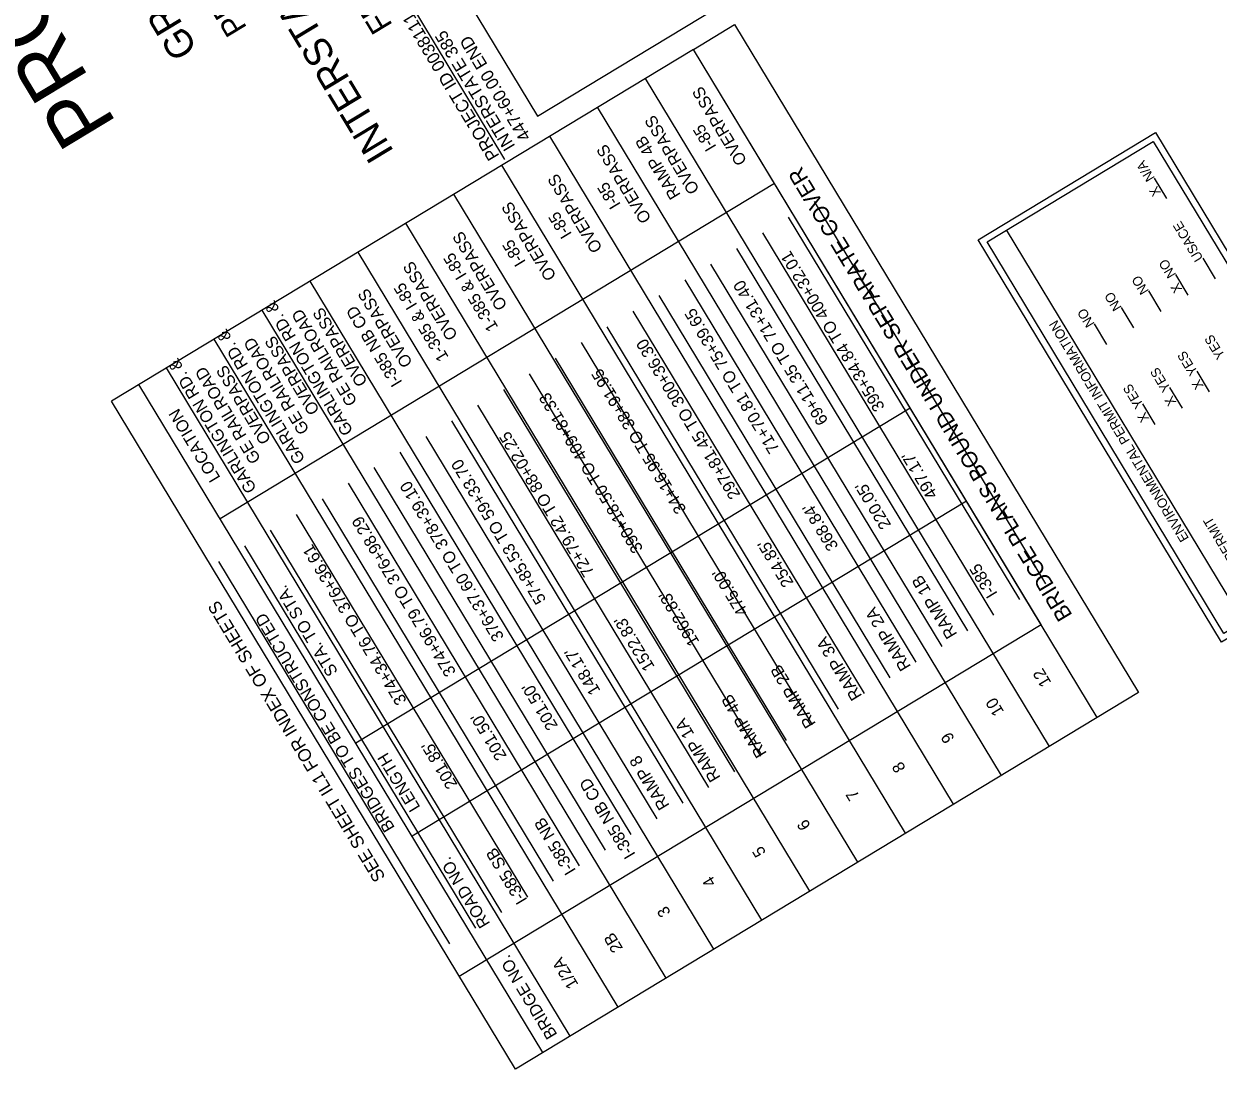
# Model space of a CAD drawing. Extents: x 2640307 to 2643631, y 679117 to 682232.
# Drawn here: x 2642228 to 2642974, y 679932 to 680585 of the extents above; entities that cross this region are included whole.
import ezdxf

# ---------------------------------------------------------------- set-up
doc = ezdxf.new("R2010")
doc.units = 0
for name, color, linetype in [('Level 3', 7, 'Continuous'), ('Level 42', 7, 'Continuous'), ('Level 63', 7, 'Continuous'), ('RD_SHT_Bndy', 7, 'Continuous'), ('RD_SHT_TX', 7, 'Continuous'), ('RD_TX_TitleSht', 7, 'Continuous')]:
    doc.layers.add(name, color=color, linetype=linetype)

msp = doc.modelspace()

# ---------------------------------------------------------------- linework, layer by layer
at = {"layer": 'Level 3'}
for p, q in [((2642646.09, 680569.52), (2642282.38, 680349.66)), ((2642863.36, 680210.08), (2642646.09, 680569.52)), ((2642898.53, 680151.89), (2642646.09, 680569.52)), ((2642868.58, 680133.78), (2642616.14, 680551.41)), ((2642838.63, 680115.67), (2642586.19, 680533.31)), ((2642808.68, 680097.57), (2642556.23, 680515.2)), ((2642778.72, 680079.46), (2642526.28, 680497.1)), ((2642696.79, 680485.65), (2642350.19, 680276.14)), ((2642748.77, 680061.36), (2642496.33, 680478.99)), ((2642718.82, 680043.25), (2642466.37, 680460.88)), ((2642688.86, 680025.15), (2642436.42, 680442.78)), ((2642658.91, 680007.04), (2642406.47, 680424.67)), ((2642628.96, 679988.94), (2642376.51, 680406.57)), ((2642599, 679970.83), (2642346.56, 680388.46)), ((2642569.05, 679952.72), (2642316.61, 680370.36)), ((2642551.93, 679942.38), (2642299.49, 680360.01)), ((2642534.82, 679932.03), (2642282.38, 680349.66)), ((2642781.63, 680345.3), (2642435.02, 680135.79)), ((2642816.8, 680287.1), (2642470.2, 680077.6)), ((2642898.53, 680151.89), (2642534.82, 679932.03))]:
    msp.add_line(p, q, dxfattribs=at)
at = {"layer": 'Level 42'}
msp.add_lwpolyline([(2642898.53, 680151.89), (2642646.09, 680569.52), (2642671.77, 680585.04), (2642924.21, 680167.4)], close=True, dxfattribs=at)
at = {"layer": 'Level 63'}
for p, q in [((2642866.28, 680235.36), (2642721.8, 680474.4)), ((2642850.1, 680225.57), (2642705.61, 680464.61)), ((2642833.9, 680215.78), (2642689.41, 680454.81)), ((2642817.7, 680205.99), (2642673.21, 680445.03)), ((2642801.51, 680196.2), (2642657.02, 680435.24)), ((2642785.32, 680186.41), (2642640.83, 680425.45)), ((2642769.11, 680176.62), (2642624.63, 680415.65)), ((2642752.93, 680166.84), (2642608.44, 680405.86)), ((2642736.73, 680157.04), (2642592.24, 680396.08)), ((2642720.53, 680147.26), (2642576.06, 680386.29)), ((2642704.34, 680137.47), (2642559.86, 680376.5)), ((2642688.14, 680127.68), (2642543.66, 680366.71)), ((2642671.95, 680117.9), (2642527.48, 680356.92)), ((2642655.76, 680108.1), (2642511.27, 680347.14)), ((2642639.56, 680098.31), (2642495.08, 680337.34)), ((2642623.44, 680088.58), (2642478.96, 680327.61)), ((2642607.26, 680078.79), (2642462.77, 680317.82)), ((2642591.07, 680069), (2642446.57, 680308.04)), ((2642574.87, 680059.22), (2642430.38, 680298.26)), ((2642558.67, 680049.43), (2642414.19, 680288.46)), ((2642542.49, 680039.63), (2642397.99, 680278.66)), ((2642526.28, 680029.84), (2642381.79, 680268.88)), ((2642510.08, 680020.06), (2642365.6, 680259.1)), ((2642493.9, 680010.28), (2642349.4, 680249.32))]:
    msp.add_line(p, q, dxfattribs=at)
at = {"layer": 'RD_SHT_Bndy'}
msp.add_line((2642989.83, 680211.75), (2642841.82, 680456.61), dxfattribs=at)
for points in [[(2642875.86, 680725.69), (2642552.94, 681259.91), (2642225.67, 681062.09), (2642548.59, 680527.87)], [(2642976.28, 680198.88), (2642824.15, 680450.56), (2642934.92, 680517.52), (2643087.05, 680265.84)], [(2642977.64, 680204.37), (2642829.64, 680449.21), (2642933.56, 680512.03), (2643081.56, 680267.19)]]:
    msp.add_lwpolyline(points, close=True, dxfattribs=at)
at = {"layer": 'RD_SHT_TX'}
for p, q in [((2642934.14, 680489.11), (2642941.9, 680476.27)), ((2642964.42, 680439.01), (2642972.18, 680426.17)), ((2642947.44, 680428.74), (2642955.2, 680415.91)), ((2642930.46, 680418.48), (2642938.22, 680405.64)), ((2642913.48, 680408.21), (2642921.24, 680395.38)), ((2642896.5, 680397.95), (2642904.26, 680385.11)), ((2642960.73, 680368.37), (2642968.49, 680355.53)), ((2642943.75, 680358.1), (2642951.5, 680345.27)), ((2642926.76, 680347.84), (2642934.52, 680335))]:
    msp.add_line(p, q, dxfattribs=at)
at = {"layer": 'RD_TX_TitleSht'}
for p, q in [((2642460.68, 680612.26), (2642528.08, 680500.75)), ((2642499.64, 679990.23), (2642863.36, 680210.08))]:
    msp.add_line(p, q, dxfattribs=at)

# ---------------------------------------------------------------- texts
at = {"layer": 'Level 3'}
for s, height, p in [('OVERPASS', 7.5, (2642679.81, 680499.8)), ('OVERPASS', 7.5, (2642650.1, 680481.84)), ('I-85 ', 7.5, (2642660.68, 680508.66)), ('OVERPASS', 7.5, (2642620, 680463.65)), ('RAMP 4B ', 7.5, (2642638.31, 680478.58)), ('BRIDGE PLANS BOUND UNDER SEPARATE COVER', 10, (2642883.23, 680215.87)), ('OVERPASS', 7.5, (2642589.44, 680445.17)), ('I-85 ', 7.5, (2642600.87, 680472.51)), ('OVERPASS', 7.5, (2642560.64, 680427.76)), ('I-85 ', 7.5, (2642570.31, 680454.04)), ('OVERPASS', 7.5, (2642529.99, 680409.24)), ('I-85 ', 7.5, (2642541.51, 680436.63)), ('395+34.84 TO 400+32.01', 7.5, (2642765.95, 680345.9)), ('OVERPASS', 7.5, (2642499.01, 680390.51)), ('1-385 & I-85 ', 7.5, (2642524.27, 680395.91)), ('1-385 & I-85 ', 7.5, (2642493.29, 680377.19)), ('69+11.35 TO 71+31.40', 7.5, (2642730.58, 680337.32)), ('OVERPASS', 7.5, (2642470.81, 680373.47)), ('GARLINGTON RD. & ', 7.5, (2642433.61, 680330.94)), ('GE RAILROAD', 7.5, (2642436.24, 680349.38)), ('OVERPASS', 7.5, (2642442.61, 680361.62)), ('I-385 NB CD', 7.5, (2642464.33, 680361.41)), ('71+70.81 TO 75+39.65', 7.5, (2642700.14, 680319.68)), ('GARLINGTON RD. & ', 7.5, (2642403.64, 680313.19)), ('GE RAILROAD', 7.5, (2642406.26, 680331.63)), ('OVERPASS', 7.5, (2642412.64, 680343.87)), ('297+81.45 TO 300+36.30', 7.5, (2642675.67, 680291.12)), ('GARLINGTON RD. & ', 7.5, (2642373.3, 680294.87)), ('GE RAILROAD', 7.5, (2642375.92, 680313.31)), ('OVERPASS', 7.5, (2642382.3, 680325.55)), ('34+16.95 TO 38+91.95', 7.5, (2642641.91, 680281.93)), ('390+18.50 TO 409+81.33', 7.5, (2642614.89, 680257.39)), ('LOCATION', 7.5, (2642350.6, 680301.8)), ('72+79.42 TO 88+02.25', 7.5, (2642584.28, 680242.65)), ("497.17'", 7.5, (2642799.02, 680291.18)), ('57+85.53 TO 59+33.70', 7.5, (2642554.25, 680225.42)), ('376+37.60 TO 378+39.10', 7.5, (2642527.97, 680202.18)), ("220.05'", 7.5, (2642769.9, 680272.27)), ("368.84'", 7.5, (2642736.93, 680258.81)), ('374+96.79 TO 376+98.29', 7.5, (2642497.91, 680180.22)), ('374+34.76 TO 376+36.61', 7.5, (2642467.12, 680162.43)), ("254.85'", 7.5, (2642708.93, 680236.1)), ("475.00'", 7.5, (2642680.56, 680217.99)), ('I-385', 7.5, (2642836.43, 680229.3)), ('STA. TO STA.', 7.5, (2642424.09, 680180.46)), ('RAMP 1B', 7.5, (2642811.21, 680203.92)), ('RAMP 1B', 7.5, (2642811.21, 680203.92)), ("1962.83'", 7.5, (2642650.03, 680199.26)), ('SEE SHEET IL1 FOR INDEX OF SHEETS', 8, (2642453.79, 680052.08)), ('RAMP 2A', 7.5, (2642782.27, 680183.8)), ('BRIDGES TO BE CONSTRUCTED', 7.5, (2642459.62, 680083.02)), ("1522.83'", 7.5, (2642622.11, 680183.6)), ('RAMP 3A', 7.5, (2642751.71, 680165.33)), ("148.17'", 7.5, (2642588.19, 680168.64)), ('RAMP 2B', 7.5, (2642722.85, 680148.02)), ('12', 7.5, (2642870.02, 680173.73)), ("201.50'", 7.5, (2642561.55, 680146.63)), ('RAMP 4B', 7.5, (2642692.2, 680129.5)), ('10', 7.5, (2642840.46, 680155.52)), ("201.50'", 7.5, (2642529.6, 680127.8)), ('RAMP 1A', 7.5, (2642663.27, 680114.36)), ('9', 7.5, (2642809.57, 680138.64)), ('LENGTH', 7.5, (2642475.58, 680095.74)), ("201.85'", 7.5, (2642498.84, 680109.96)), ('RAMP 8', 7.5, (2642631.38, 680096.87)), ('8', 7.5, (2642779.01, 680120.17)), ('I-385 NB CD', 7.5, (2642610.1, 680066.3)), ('7', 7.5, (2642750.2, 680102.76)), ('I-385 NB', 7.5, (2642572.87, 680056.22)), ('6', 7.5, (2642719.65, 680084.08)), ('I-385 SB', 7.5, (2642542.44, 680037.83)), ('5', 7.5, (2642691.67, 680067.38)), ('ROAD NO.', 7.5, (2642519.25, 680023.03)), ('4', 7.5, (2642660.57, 680048.58)), ('3', 7.5, (2642632.15, 680029.84)), ('2B', 7.5, (2642602.24, 680007.62)), ('BRIDGE NO.', 7.5, (2642561.21, 679953.61)), ('1/2A', 7.5, (2642574.41, 679984.93))]:
    msp.add_text(s, height=height, rotation=121.15134, dxfattribs=at).set_placement(p)
at = {"layer": 'RD_SHT_TX'}
for s, height, rotation, p in [('PROPOSED PLANS', 37.5, 121.15134, (2642285.9, 680523.05)), ('INTERSTATE 85 /  385 INTERCHANGE', 17.5, 121.14982, (2642459.22, 680505.53)), ('FROM:  0.20 MILES SOUTH OF S-326', 14, 121.14982, (2642458.33, 680584.66)), ('PROJECT ID 0038111 - R02', 14, 121.15134, (2642367.3, 680583)), ('GREENVILLE COUNTY', 17.5, 121.14982, (2642336.5, 680569.72)), ('N/A', 6, 121.15134, (2642934.67, 680489.15)), ('X', 6, 121.15134, (2642938.55, 680479.92)), ('USACE', 6, 121.15134, (2642964.95, 680439.05)), ('NO', 6, 121.15134, (2642947.97, 680428.78)), ('NO', 6, 121.15134, (2642930.99, 680418.52)), ('X', 6, 121.15134, (2642951.86, 680419.55)), ('NO', 6, 121.15134, (2642914.01, 680408.26)), ('NO', 6, 121.15134, (2642897.03, 680397.99)), ('ENVIRONMENTAL PERMIT INFORMATION', 6, 121.15134, (2642955.99, 680263.87)), ('YES', 6, 121.15134, (2642978.64, 680378.05)), ('YES', 6, 121.15134, (2642961.66, 680367.78)), ('YES', 6, 121.15134, (2642944.68, 680357.52)), ('X', 6, 121.15134, (2642965.14, 680359.18)), ('YES', 6, 121.15134, (2642927.7, 680347.25)), ('X', 6, 121.15134, (2642948.16, 680348.91)), ('X', 6, 121.15134, (2642931.18, 680338.65)), ('USACE PERMIT', 6, 121.15134, (2643000.71, 680226.46))]:
    msp.add_text(s, height=height, rotation=rotation, dxfattribs=at).set_placement(p)
at = {"layer": 'RD_TX_TitleSht'}
for s, p in [('PROJECT ID 0038111-R02', (2642525.02, 680503.02)), ('INTERSTATE 385 ', (2642534.92, 680509)), ('447+60.00 END', (2642544.83, 680514.99))]:
    msp.add_text(s, height=7.825, rotation=121.15134, dxfattribs=at).set_placement(p)

doc.saveas('drawing.dxf')
